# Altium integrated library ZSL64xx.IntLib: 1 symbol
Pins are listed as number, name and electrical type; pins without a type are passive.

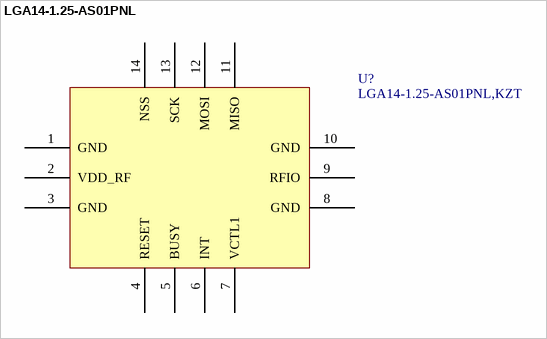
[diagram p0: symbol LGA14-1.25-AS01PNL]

## LGA14-1.25-AS01PNL
designator U?, comment LGA14-1.25-AS01PNL,KZT
LGA14-1.25-AS01PNL,KZT,LGA-8X8-14; 物料代码: 20.15.00019; 名称: 测试座; PCB备注: 210107hcj; 器件优选方案: 待导入物料
footprint LGA14-1.25-AS01PNL
pins: 1 GND, 2 VDD_RF, 3 GND, 4 RESET, 5 BUSY, 6 INT, 7 VCTL1, 8 GND, 9 RFIO, 10 GND, 11 MISO, 12 MOSI, 13 SCK, 14 NSS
